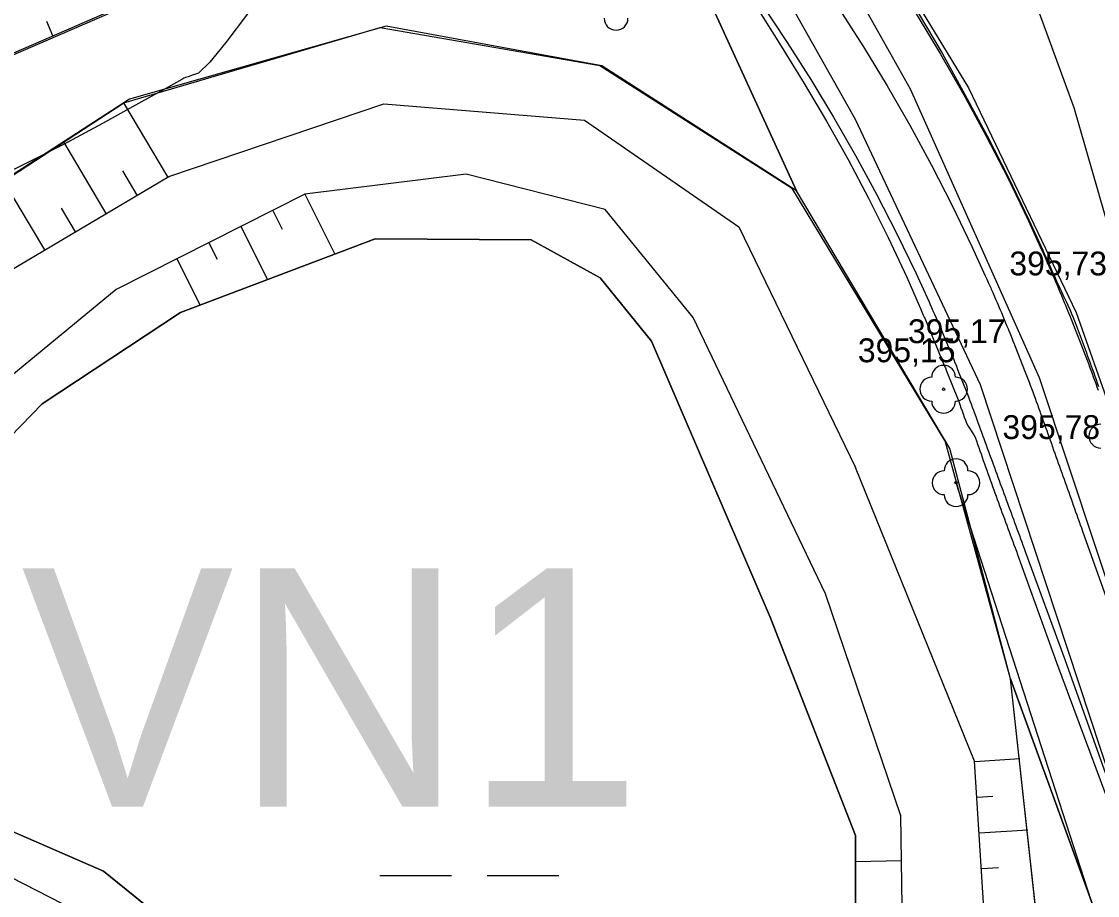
# Model space of a CAD drawing. Extents: x -574342 to -508101, y -1143544 to -1123894.
# Drawn here: x -508495.78 to -508450.68, y -1143192.58 to -1143155.94 of the extents above; entities that cross this region are included whole.
import ezdxf

# ---------------------------------------------------------------- set-up
doc = ezdxf.new("R2010")
doc.units = 0
for name, color, linetype in [('01_PARCELY_NAVRH_PC', 7, 'Continuous'), ('01_PARCELY_NAVRH_VHO', 7, 'Continuous'), ('01_PARCELY_NAVRH_ŽP', 7, 'Continuous'), ('05_VHO_V_NÁDRŽ_STAV', 7, 'Continuous'), ('1000', 7, 'Continuous'), ('21', 7, 'Continuous'), ('37', 7, 'Continuous'), ('43', 7, 'Continuous'), ('51', 7, 'Continuous'), ('54', 7, 'Continuous'), ('55', 7, 'Continuous'), ('60', 7, 'Continuous'), ('61', 7, 'Continuous'), ('Level 255', 7, 'Continuous'), ('VRST VEDL', 7, 'Continuous')]:
    doc.layers.add(name, color=color, linetype=linetype)

msp = doc.modelspace()

# ---------------------------------------------------------------- linework, layer by layer
at = {"layer": '01_PARCELY_NAVRH_PC'}
msp.add_lwpolyline([(-508445.99, -1143206.42), (-508454.33, -1143183.49), (-508456.87, -1143173.84), (-508463.3, -1143163.03), (-508476.26, -1143134.7), (-508479.46, -1143126.74), (-508474.05, -1143124.14), (-508467.92, -1143139.18), (-508459.97, -1143152.33), (-508456.09, -1143158.71), (-508451.57, -1143168.14), (-508437.66, -1143207.58)], dxfattribs=at)
at = {"layer": '01_PARCELY_NAVRH_VHO'}
for points in [[(-508497.89, -1143158.09), (-508486.83, -1143153.3), (-508481.34, -1143149.03), (-508479.12, -1143143.52), (-508479.68, -1143136.88), (-508476.26, -1143134.7), (-508479.46, -1143126.74), (-508483.82, -1143117.57), (-508484.878, -1143116.058)], [(-508452.72, -1143198.2), (-508454.33, -1143183.49), (-508456.87, -1143173.84), (-508463.3, -1143163.03), (-508471.45, -1143157.79), (-508480.5, -1143156.13), (-508491.25, -1143159.19), (-508499.36, -1143164.43)]]:
    msp.add_lwpolyline(points, dxfattribs=at)
at = {"layer": '01_PARCELY_NAVRH_ŽP'}
msp.add_lwpolyline([(-508476.398, -1143116.058), (-508474.05, -1143124.14), (-508467.92, -1143139.18), (-508459.97, -1143152.33), (-508456.09, -1143158.71), (-508451.57, -1143168.14), (-508437.66, -1143207.58), (-508425.52, -1143241.92), (-508422.7, -1143249.88), (-508420.04, -1143252.1), (-508417.38, -1143252.95), (-508415.56, -1143252.78), (-508448.24, -1143160.16), (-508453.75, -1143145.01), (-508465.11, -1143123.03), (-508467.879, -1143116.058)], dxfattribs=at)
for points in [[(-508521.06, -1143176.58), (-508518.2, -1143171.1), (-508515.68, -1143172.08), (-508512.27, -1143171.56), (-508509.12, -1143169.33), (-508497.89, -1143158.09), (-508486.83, -1143153.3), (-508481.34, -1143149.03), (-508479.12, -1143143.52), (-508479.68, -1143136.88), (-508476.26, -1143134.7), (-508463.3, -1143163.03), (-508471.45, -1143157.79), (-508480.5, -1143156.13), (-508491.25, -1143159.19), (-508499.36, -1143164.43), (-508507.52, -1143173.92), (-508509.38, -1143179.27), (-508513.26, -1143177.6)], [(-508455.43, -1143236.54), (-508453.14, -1143234.1), (-508452.04, -1143229.57), (-508450.69, -1143221.56), (-508452.8, -1143209.75), (-508452.72, -1143198.2), (-508454.33, -1143183.49), (-508445.99, -1143206.42), (-508432.73, -1143240.34), (-508433.72, -1143240.11), (-508438.05, -1143241.09), (-508444.11, -1143244.2), (-508446.56, -1143243.12), (-508452.58, -1143244.39)]]:
    msp.add_lwpolyline(points, close=True, dxfattribs=at)
at = {"layer": '05_VHO_V_NÁDRŽ_STAV'}
msp.add_lwpolyline([(-508460.83, -1143194.159), (-508460.83, -1143190.06), (-508464.4, -1143180.91), (-508469.37, -1143169.34), (-508471.53, -1143166.68), (-508474.42, -1143165.09), (-508480.95, -1143165.04), (-508489.11, -1143168.14), (-508494.91, -1143171.96), (-508499.81, -1143177.01), (-508501.3, -1143181.37), (-508501.49, -1143182.82), (-508501.26, -1143185.56), (-508499.61, -1143188.4), (-508492.34, -1143191.56), (-508489.27, -1143194.04)], dxfattribs=at)
at = {"layer": '1000'}
for points in [[(-508465.065, -1143155.16), (-508463.936, -1143156.975), (-508462.971, -1143158.539), (-508462.033, -1143160.119), (-508461.133, -1143161.72), (-508460.274, -1143163.343), (-508459.455, -1143164.986), (-508458.678, -1143166.649), (-508458.16, -1143167.839), (-508458.101, -1143167.974), (-508458.042, -1143168.109), (-508457.983, -1143168.244), (-508457.945, -1143168.331), (-508457.924, -1143168.379), (-508457.866, -1143168.514), (-508457.809, -1143168.65), (-508457.752, -1143168.786), (-508457.695, -1143168.922), (-508457.638, -1143169.058), (-508457.582, -1143169.194), (-508457.527, -1143169.33), (-508457.471, -1143169.467), (-508457.417, -1143169.604), (-508457.362, -1143169.741), (-508457.305, -1143169.876), (-508457.247, -1143170.012), (-508457.241, -1143170.025), (-508457.189, -1143170.147), (-508457.132, -1143170.283), (-508457.075, -1143170.419), (-508457.058, -1143170.46), (-508457.019, -1143170.555), (-508456.963, -1143170.691), (-508456.551, -1143171.724), (-508456.497, -1143171.864), (-508456.45, -1143171.995), (-508456.403, -1143172.126), (-508456.356, -1143172.257), (-508456.31, -1143172.387), (-508456.264, -1143172.518), (-508456.218, -1143172.65), (-508456.172, -1143172.781), (-508456.096, -1143172.901), (-508456.02, -1143173.021), (-508455.944, -1143173.141), (-508455.868, -1143173.262), (-508455.801, -1143173.386), (-508455.796, -1143173.4), (-508455.796, -1143173.402), (-508455.754, -1143173.522), (-508455.706, -1143173.658), (-508455.659, -1143173.794), (-508455.611, -1143173.931), (-508455.563, -1143174.067), (-508455.515, -1143174.203), (-508455.467, -1143174.339), (-508455.419, -1143174.475), (-508455.37, -1143174.612), (-508455.322, -1143174.748), (-508455.274, -1143174.884), (-508455.225, -1143175.02), (-508455.177, -1143175.156), (-508455.128, -1143175.292), (-508455.079, -1143175.428), (-508455.03, -1143175.564), (-508454.981, -1143175.699), (-508454.932, -1143175.835), (-508454.883, -1143175.971), (-508454.833, -1143176.107), (-508454.784, -1143176.243), (-508454.735, -1143176.378), (-508454.685, -1143176.514), (-508454.635, -1143176.649), (-508454.586, -1143176.785), (-508454.536, -1143176.921), (-508454.486, -1143177.056), (-508454.436, -1143177.192), (-508454.386, -1143177.327), (-508454.335, -1143177.463), (-508454.285, -1143177.598), (-508454.235, -1143177.733), (-508454.184, -1143177.869), (-508454.134, -1143178.004), (-508454.083, -1143178.139), (-508454.032, -1143178.274), (-508452.403, -1143182.806), (-508449.367, -1143190.95)], [(-508464.862, -1143155.027), (-508463.69, -1143156.813), (-508462.697, -1143158.368), (-508461.74, -1143159.946), (-508460.822, -1143161.546), (-508459.942, -1143163.168), (-508459.101, -1143164.81), (-508458.299, -1143166.471), (-508457.756, -1143167.658), (-508457.696, -1143167.794), (-508457.636, -1143167.929), (-508457.576, -1143168.065), (-508457.538, -1143168.152), (-508457.516, -1143168.2), (-508457.457, -1143168.336), (-508457.398, -1143168.472), (-508457.339, -1143168.608), (-508457.281, -1143168.744), (-508457.222, -1143168.88), (-508457.164, -1143169.017), (-508457.106, -1143169.153), (-508457.049, -1143169.289), (-508456.992, -1143169.426), (-508456.935, -1143169.563), (-508456.878, -1143169.7), (-508456.821, -1143169.837), (-508456.816, -1143169.85), (-508456.765, -1143169.974), (-508456.709, -1143170.111), (-508456.654, -1143170.248), (-508456.637, -1143170.29), (-508456.598, -1143170.386), (-508456.543, -1143170.523), (-508456.135, -1143171.564), (-508456.081, -1143171.706), (-508456.032, -1143171.836), (-508455.982, -1143171.967), (-508455.933, -1143172.098), (-508455.884, -1143172.229), (-508455.835, -1143172.36), (-508455.787, -1143172.491), (-508455.739, -1143172.622), (-508455.691, -1143172.753), (-508455.643, -1143172.884), (-508455.595, -1143173.016), (-508455.548, -1143173.147), (-508455.501, -1143173.279), (-508455.496, -1143173.293), (-508455.495, -1143173.295), (-508455.452, -1143173.414), (-508455.402, -1143173.55), (-508455.352, -1143173.685), (-508455.302, -1143173.821), (-508455.252, -1143173.956), (-508455.202, -1143174.092), (-508455.153, -1143174.227), (-508455.103, -1143174.363), (-508455.053, -1143174.498), (-508455.003, -1143174.634), (-508454.953, -1143174.77), (-508454.903, -1143174.905), (-508454.854, -1143175.041), (-508454.804, -1143175.176), (-508454.754, -1143175.312), (-508454.704, -1143175.447), (-508454.654, -1143175.583), (-508454.605, -1143175.719), (-508454.555, -1143175.854), (-508454.505, -1143175.99), (-508454.455, -1143176.125), (-508454.405, -1143176.261), (-508454.355, -1143176.396), (-508454.306, -1143176.532), (-508454.256, -1143176.668), (-508454.206, -1143176.803), (-508454.156, -1143176.939), (-508454.106, -1143177.074), (-508454.056, -1143177.21), (-508454.007, -1143177.345), (-508453.957, -1143177.481), (-508453.907, -1143177.617), (-508453.857, -1143177.752), (-508453.807, -1143177.888), (-508453.757, -1143178.023), (-508453.708, -1143178.159), (-508452.046, -1143182.679), (-508449.13, -1143190.865)], [(-508458.282, -1143155.62), (-508457.262, -1143157.304), (-508456.282, -1143159.012), (-508455.342, -1143160.742), (-508454.445, -1143162.495), (-508453.589, -1143164.268), (-508453.01, -1143165.535), (-508452.945, -1143165.679), (-508452.881, -1143165.823), (-508452.817, -1143165.968), (-508452.776, -1143166.061), (-508452.754, -1143166.113), (-508452.69, -1143166.258), (-508452.627, -1143166.403), (-508452.565, -1143166.548), (-508452.502, -1143166.693), (-508452.44, -1143166.839), (-508452.378, -1143166.984), (-508452.316, -1143167.13), (-508452.255, -1143167.275), (-508452.194, -1143167.421), (-508452.133, -1143167.567), (-508452.072, -1143167.713), (-508452.012, -1143167.859), (-508452.006, -1143167.873), (-508451.952, -1143168.006), (-508451.892, -1143168.152), (-508451.833, -1143168.299), (-508451.815, -1143168.343), (-508451.774, -1143168.445), (-508451.715, -1143168.592), (-508451.28, -1143169.703), (-508451.222, -1143169.854), (-508451.169, -1143169.993), (-508451.116, -1143170.133), (-508451.064, -1143170.272), (-508451.012, -1143170.412), (-508450.96, -1143170.552), (-508450.908, -1143170.692), (-508450.857, -1143170.832), (-508450.805, -1143170.972), (-508450.754, -1143171.112), (-508450.704, -1143171.252), (-508450.653, -1143171.392)], [(-508458.193, -1143155.565), (-508457.198, -1143157.266), (-508456.241, -1143158.989), (-508455.309, -1143160.725), (-508454.415, -1143162.48), (-508453.559, -1143164.254), (-508452.977, -1143165.52), (-508452.912, -1143165.664), (-508452.847, -1143165.808), (-508452.783, -1143165.953), (-508452.741, -1143166.046), (-508452.718, -1143166.097), (-508452.654, -1143166.242), (-508452.59, -1143166.386), (-508452.526, -1143166.531), (-508452.462, -1143166.676), (-508452.398, -1143166.821), (-508452.332, -1143166.965), (-508452.264, -1143167.108), (-508452.196, -1143167.251), (-508452.128, -1143167.394), (-508452.061, -1143167.537), (-508451.993, -1143167.68), (-508451.926, -1143167.824), (-508451.919, -1143167.837), (-508451.858, -1143167.967), (-508451.794, -1143168.112), (-508451.737, -1143168.26), (-508451.72, -1143168.305), (-508451.68, -1143168.408), (-508451.623, -1143168.555), (-508451.202, -1143169.673), (-508451.146, -1143169.825), (-508451.095, -1143169.965), (-508451.044, -1143170.105), (-508450.993, -1143170.246), (-508450.942, -1143170.386), (-508450.892, -1143170.527), (-508450.842, -1143170.667), (-508450.793, -1143170.808), (-508450.744, -1143170.949), (-508450.695, -1143171.09), (-508450.646, -1143171.231)]]:
    msp.add_lwpolyline(points, dxfattribs=at)
at = {"layer": '21'}
msp.add_lwpolyline([(-508461.516, -1143155.387), (-508460.489, -1143156.994), (-508459.501, -1143158.625), (-508458.552, -1143160.279), (-508457.642, -1143161.955), (-508456.773, -1143163.652), (-508455.944, -1143165.37), (-508455.383, -1143166.596), (-508455.321, -1143166.736), (-508455.259, -1143166.876), (-508455.197, -1143167.016), (-508455.157, -1143167.106), (-508455.135, -1143167.157), (-508455.074, -1143167.297), (-508455.013, -1143167.437), (-508454.952, -1143167.578), (-508454.891, -1143167.719), (-508454.831, -1143167.859), (-508454.771, -1143168), (-508454.711, -1143168.141), (-508454.652, -1143168.282), (-508454.593, -1143168.424), (-508454.534, -1143168.565), (-508454.475, -1143168.707), (-508454.417, -1143168.848), (-508454.411, -1143168.861), (-508454.359, -1143168.99), (-508454.301, -1143169.132), (-508454.243, -1143169.274), (-508454.226, -1143169.317), (-508454.186, -1143169.416), (-508454.129, -1143169.558), (-508453.707, -1143170.634), (-508453.652, -1143170.78), (-508453.6, -1143170.915), (-508453.549, -1143171.05), (-508453.498, -1143171.185), (-508453.448, -1143171.32), (-508453.398, -1143171.456), (-508453.347, -1143171.591), (-508453.298, -1143171.727), (-508453.248, -1143171.862), (-508453.199, -1143171.998), (-508453.15, -1143172.134), (-508453.101, -1143172.27), (-508453.052, -1143172.406), (-508453.047, -1143172.42), (-508453.046, -1143172.422), (-508453.004, -1143172.542), (-508452.955, -1143172.678), (-508452.907, -1143172.814), (-508452.858, -1143172.95), (-508452.81, -1143173.086), (-508452.761, -1143173.222), (-508452.713, -1143173.358), (-508452.664, -1143173.494), (-508452.616, -1143173.63), (-508452.567, -1143173.766), (-508452.519, -1143173.902), (-508452.47, -1143174.038), (-508452.422, -1143174.174), (-508452.374, -1143174.311), (-508452.325, -1143174.447), (-508452.277, -1143174.583), (-508452.228, -1143174.719), (-508452.18, -1143174.855), (-508452.131, -1143174.991), (-508452.083, -1143175.127), (-508452.034, -1143175.263), (-508451.986, -1143175.399), (-508451.937, -1143175.535), (-508451.889, -1143175.671), (-508451.84, -1143175.807), (-508451.792, -1143175.943), (-508451.743, -1143176.079), (-508451.695, -1143176.215), (-508451.646, -1143176.351), (-508451.598, -1143176.487), (-508451.55, -1143176.623), (-508451.501, -1143176.759), (-508451.453, -1143176.895), (-508451.404, -1143177.032), (-508451.356, -1143177.168), (-508451.307, -1143177.304), (-508449.691, -1143181.84)], dxfattribs=at)
at = {"layer": '37'}
for points in [[(-508473.82, -1143129.8), (-508468.34, -1143141.31), (-508458.53, -1143158.76), (-508453.13, -1143170.86), (-508439.96, -1143210.5), (-508427.56, -1143241.73), (-508421.57, -1143265.72), (-508416.35, -1143292.6), (-508412.42, -1143304.7), (-508408.82, -1143311.83)], [(-508473.82, -1143129.8), (-508468.34, -1143141.31), (-508458.53, -1143158.76), (-508453.13, -1143170.86), (-508439.96, -1143210.5), (-508427.56, -1143241.73), (-508421.57, -1143265.72), (-508416.35, -1143292.6), (-508412.42, -1143304.7), (-508408.82, -1143311.83)], [(-508408.82, -1143311.83), (-508404.37, -1143317.04), (-508398.21, -1143321.18), (-508393.66, -1143322.44), (-508393.79, -1143324.58), (-508400.56, -1143323.11), (-508406.32, -1143319.06), (-508411.41, -1143313.16), (-508415.31, -1143305.9), (-508419.33, -1143292.88), (-508424.96, -1143264.72), (-508428.49, -1143248.11), (-508430.27, -1143242.09), (-508442.28, -1143211.48), (-508455.59, -1143171.17), (-508460.82, -1143160.05), (-508470.5, -1143142.85)], [(-508408.82, -1143311.83), (-508404.37, -1143317.04), (-508398.21, -1143321.18), (-508393.66, -1143322.44), (-508393.79, -1143324.58), (-508400.56, -1143323.11), (-508406.32, -1143319.06), (-508411.41, -1143313.16), (-508415.31, -1143305.9), (-508419.33, -1143292.88), (-508424.96, -1143264.72), (-508428.49, -1143248.11), (-508430.27, -1143242.09), (-508442.28, -1143211.48), (-508455.59, -1143171.17), (-508460.82, -1143160.05), (-508470.5, -1143142.85)]]:
    msp.add_lwpolyline(points, dxfattribs=at)
at = {"layer": '43'}
for p, q in [((-508480.755, -1143191.736), (-508477.755, -1143191.736)), ((-508476.255, -1143191.736), (-508473.255, -1143191.736))]:
    msp.add_line(p, q, dxfattribs=at)
at = {"layer": '51'}
for points in [[(-508501.3, -1143181.37), (-508499.81, -1143177.01), (-508494.91, -1143171.96), (-508489.11, -1143168.14), (-508480.95, -1143165.04), (-508474.42, -1143165.09), (-508471.53, -1143166.68), (-508469.37, -1143169.34), (-508464.4, -1143180.91), (-508460.83, -1143190.06), (-508460.83, -1143200.16)], [(-508501.3, -1143181.37), (-508499.81, -1143177.01), (-508494.91, -1143171.96), (-508489.11, -1143168.14), (-508480.95, -1143165.04), (-508474.42, -1143165.09), (-508471.53, -1143166.68), (-508469.37, -1143169.34), (-508464.4, -1143180.91), (-508460.83, -1143190.06), (-508460.83, -1143200.16)], [(-508489.27, -1143194.04), (-508492.34, -1143191.56), (-508499.61, -1143188.4), (-508501.26, -1143185.56), (-508501.49, -1143182.82)], [(-508489.27, -1143194.04), (-508492.34, -1143191.56), (-508499.61, -1143188.4), (-508501.26, -1143185.56), (-508501.49, -1143182.82)]]:
    msp.add_lwpolyline(points, dxfattribs=at)
at = {"layer": '54'}
for centre in [(-508457.13, -1143171.35), (-508456.61, -1143175.27)]:
    msp.add_circle(centre, 0.05, dxfattribs=at)
for centre, start, end in [((-508470.86, -1143155.8), 180, 0), ((-508457.13, -1143170.85), 0, 180), ((-508457.63, -1143171.35), 90, 270), ((-508456.63, -1143171.35), 270, 90), ((-508457.13, -1143171.85), 180, 0), ((-508450.54, -1143173.32), 90, 270), ((-508456.61, -1143174.77), 0, 180), ((-508457.11, -1143175.27), 90, 270), ((-508456.11, -1143175.27), 270, 90), ((-508456.61, -1143175.77), 180, 0)]:
    msp.add_arc(centre, 0.5, start, end, dxfattribs=at)
at = {"layer": '55'}
for points in [[(-508471.007, -1143116.058), (-508468.39, -1143122.87), (-508456.91, -1143145.22), (-508451.68, -1143159.54), (-508438.58, -1143205.02)], [(-508471.007, -1143116.058), (-508468.39, -1143122.87), (-508456.91, -1143145.22), (-508451.68, -1143159.54), (-508438.58, -1143205.02)], [(-508435.13, -1143235.61), (-508444.83, -1143211.72), (-508456.61, -1143175.27)], [(-508435.13, -1143235.61), (-508444.83, -1143211.72), (-508456.61, -1143175.27)]]:
    msp.add_lwpolyline(points, dxfattribs=at)
at = {"layer": '60'}
for points in [[(-508515.74, -1143172.05), (-508512.28, -1143171.53), (-508508.56, -1143168.5), (-508497.82, -1143157.99), (-508486.77, -1143153.18), (-508481.27, -1143148.82), (-508479.19, -1143143.42), (-508479.72, -1143136.69), (-508476.24, -1143134.48), (-508476.7, -1143133.48), (-508480.34, -1143134.37), (-508481.13, -1143128.49), (-508479.36, -1143127.67), (-508479.81, -1143126.52), (-508482.03, -1143126.91), (-508483.98, -1143117.49), (-508484.986, -1143116.058)], [(-508515.74, -1143172.05), (-508512.28, -1143171.53), (-508508.56, -1143168.5), (-508497.82, -1143157.99), (-508486.77, -1143153.18), (-508481.27, -1143148.82), (-508479.19, -1143143.42), (-508479.72, -1143136.69), (-508476.24, -1143134.48), (-508476.7, -1143133.48), (-508480.34, -1143134.37), (-508481.13, -1143128.49), (-508479.36, -1143127.67), (-508479.81, -1143126.52), (-508482.03, -1143126.91), (-508483.98, -1143117.49), (-508484.986, -1143116.058)], [(-508509.56, -1143179.75), (-508507.59, -1143174.03), (-508499.59, -1143164.63), (-508491.49, -1143159.34), (-508480.74, -1143156.18), (-508471.54, -1143157.78), (-508463.5, -1143162.91), (-508457.05, -1143173.57)], [(-508509.56, -1143179.75), (-508507.59, -1143174.03), (-508499.59, -1143164.63), (-508491.49, -1143159.34), (-508480.74, -1143156.18), (-508471.54, -1143157.78), (-508463.5, -1143162.91), (-508457.05, -1143173.57)], [(-508506.58, -1143184.83), (-508505.59, -1143179.84), (-508503.86, -1143175), (-508497.84, -1143167.31), (-508489.61, -1143162.43), (-508480.59, -1143159.39), (-508472.18, -1143160.07), (-508465.72, -1143164.54), (-508460.82, -1143174.63)], [(-508506.58, -1143184.83), (-508505.59, -1143179.84), (-508503.86, -1143175), (-508497.84, -1143167.31), (-508489.61, -1143162.43), (-508480.59, -1143159.39), (-508472.18, -1143160.07), (-508465.72, -1143164.54), (-508460.82, -1143174.63)], [(-508455.56, -1143236.37), (-508453.06, -1143233.89), (-508451.99, -1143229.27), (-508454.51, -1143221.16), (-508458.09, -1143209.77), (-508458.76, -1143200.63), (-508458.93, -1143189.23), (-508462.08, -1143179.93), (-508467.63, -1143168.34), (-508471.31, -1143163.81), (-508477.14, -1143162.33), (-508483.91, -1143163.18), (-508491.81, -1143167.17), (-508499.86, -1143173.8), (-508502.62, -1143178.78)], [(-508455.56, -1143236.37), (-508453.06, -1143233.89), (-508451.99, -1143229.27), (-508454.51, -1143221.16), (-508458.09, -1143209.77), (-508458.76, -1143200.63), (-508458.93, -1143189.23), (-508462.08, -1143179.93), (-508467.63, -1143168.34), (-508471.31, -1143163.81), (-508477.14, -1143162.33), (-508483.91, -1143163.18), (-508491.81, -1143167.17), (-508499.86, -1143173.8), (-508502.62, -1143178.78)], [(-508450.7, -1143221.55), (-508452.82, -1143209.68), (-508452.74, -1143198.02), (-508454.33, -1143183.49), (-508457.05, -1143173.57)], [(-508450.7, -1143221.55), (-508452.82, -1143209.68), (-508452.74, -1143198.02), (-508454.33, -1143183.49), (-508457.05, -1143173.57)], [(-508450.7, -1143221.55), (-508455.37, -1143207.46), (-508455.25, -1143196.19), (-508455.84, -1143186.95), (-508460.82, -1143174.63)], [(-508450.7, -1143221.55), (-508455.37, -1143207.46), (-508455.25, -1143196.19), (-508455.84, -1143186.95), (-508460.82, -1143174.63)], [(-508502.62, -1143178.78), (-508502.72, -1143182.77), (-508502.79, -1143186.19), (-508500.02, -1143189.86), (-508493.53, -1143193.19), (-508490.45, -1143195.53), (-508485.71, -1143201.99), (-508472.29, -1143227.39), (-508470.21, -1143235.36), (-508466.87, -1143240.4), (-508461.84, -1143241.3), (-508457.74, -1143240.31)], [(-508502.62, -1143178.78), (-508502.72, -1143182.77), (-508502.79, -1143186.19), (-508500.02, -1143189.86), (-508493.53, -1143193.19), (-508490.45, -1143195.53), (-508485.71, -1143201.99), (-508472.29, -1143227.39), (-508470.21, -1143235.36), (-508466.87, -1143240.4), (-508461.84, -1143241.3), (-508457.74, -1143240.31)]]:
    msp.add_lwpolyline(points, dxfattribs=at)
at = {"layer": '61'}
for p, q in [((-508494.466, -1143156.53), (-508494.723, -1143155.939)), ((-508494.466, -1143156.53), (-508494.723, -1143155.939)), ((-508489.645, -1143162.451), (-508491.49, -1143159.34)), ((-508489.645, -1143162.451), (-508491.49, -1143159.34)), ((-508492.226, -1143163.981), (-508494.004, -1143160.982)), ((-508492.226, -1143163.981), (-508494.004, -1143160.982)), ((-508490.936, -1143163.216), (-508491.539, -1143162.199)), ((-508490.936, -1143163.216), (-508491.539, -1143162.199)), ((-508494.806, -1143165.511), (-508496.518, -1143162.624)), ((-508494.806, -1143165.511), (-508496.518, -1143162.624)), ((-508483.91, -1143163.18), (-508482.645, -1143165.684)), ((-508483.91, -1143163.18), (-508482.645, -1143165.684)), ((-508493.516, -1143164.746), (-508494.097, -1143163.766)), ((-508493.516, -1143164.746), (-508494.097, -1143163.766)), ((-508485.249, -1143163.856), (-508484.851, -1143164.643)), ((-508485.249, -1143163.856), (-508484.851, -1143164.643)), ((-508486.588, -1143164.532), (-508485.465, -1143166.755)), ((-508486.588, -1143164.532), (-508485.465, -1143166.755)), ((-508487.927, -1143165.209), (-508487.577, -1143165.902)), ((-508487.927, -1143165.209), (-508487.577, -1143165.902)), ((-508489.266, -1143165.885), (-508488.285, -1143167.827)), ((-508489.266, -1143165.885), (-508488.285, -1143167.827)), ((-508455.82, -1143186.96), (-508453.935, -1143186.838)), ((-508455.82, -1143186.96), (-508453.935, -1143186.838)), ((-508455.723, -1143188.457), (-508455.073, -1143188.415)), ((-508455.723, -1143188.457), (-508455.073, -1143188.415)), ((-508455.626, -1143189.954), (-508453.608, -1143189.823)), ((-508455.626, -1143189.954), (-508453.608, -1143189.823)), ((-508458.902, -1143191.13), (-508460.83, -1143191.159)), ((-508458.902, -1143191.13), (-508460.83, -1143191.159)), ((-508455.528, -1143191.451), (-508454.835, -1143191.405)), ((-508455.528, -1143191.451), (-508454.835, -1143191.405))]:
    msp.add_line(p, q, dxfattribs=at)
at = {"layer": 'VRST VEDL'}
msp.add_lwpolyline([(-508486.311, -1143155.618), (-508487.209, -1143156.812), (-508487.892, -1143157.638), (-508488.361, -1143158.097), (-508488.615, -1143158.187), (-508488.796, -1143158.251), (-508488.902, -1143158.289), (-508488.935, -1143158.3), (-508488.972, -1143158.316), (-508489.014, -1143158.336), (-508489.06, -1143158.361), (-508489.637, -1143158.683), (-508490.746, -1143159.301), (-508492.385, -1143160.215), (-508494.022, -1143161.088), (-508495.654, -1143161.919), (-508497.284, -1143162.707)], dxfattribs=at)

# ---------------------------------------------------------------- texts
at = {"layer": '05_VHO_V_NÁDRŽ_STAV'}
msp.add_text('VN1', height=10, dxfattribs=at).set_placement((-508495.796, -1143188.857))
msp.add_text('VN1', height=10, dxfattribs=at).set_placement((-508495.796, -1143188.857))
at = {"layer": 'Level 255'}
for s, p in [('395,73', (-508454.375, -1143166.58)), ('395,17', (-508458.625, -1143169.42)), ('395,15', (-508460.725, -1143170.22)), ('395,78', (-508454.665, -1143173.44))]:
    msp.add_text(s, height=1, dxfattribs=at).set_placement(p)

doc.saveas('drawing.dxf')
